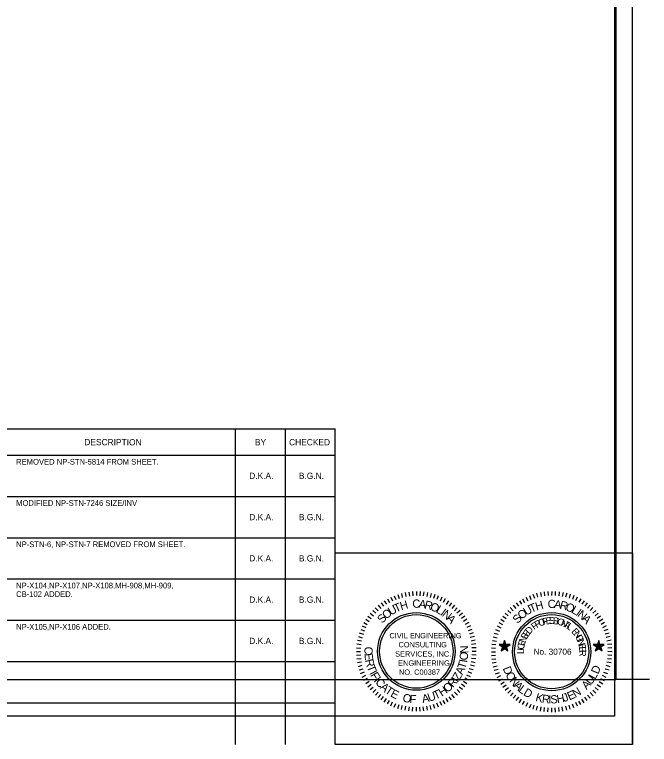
# Model space of a CAD drawing. Extents: x 260980 to 263829, y 322034 to 323393.
# Drawn here: x 262340 to 262786, y 322332 to 322845 of the extents above; entities that cross this region are included whole.
import ezdxf

# ---------------------------------------------------------------- set-up
doc = ezdxf.new("R2010")
doc.units = 0
for name, color, linetype in [('Level 1', 7, 'Continuous'), ('Level 2', 7, 'Continuous'), ('Level 23', 7, 'Continuous'), ('Level 3', 7, 'Continuous'), ('Level 5', 7, 'Continuous'), ('RD_SHT_SEAL_KA', 7, 'Continuous'), ('RD_SHT_TX', 7, 'Continuous')]:
    doc.layers.add(name, color=color, linetype=linetype)

msp = doc.modelspace()

# ---------------------------------------------------------------- linework, layer by layer
at = {"layer": 'Level 1'}
msp.add_lwpolyline([(262565.22, 322466.63), (262774.17, 322466.63), (262774.17, 322331.93), (262565.22, 322331.93)], close=True, dxfattribs=at)
at = {"layer": 'Level 2'}
msp.add_line((262761.95, 322377.79), (262785.98, 322377.79), dxfattribs=at)
at = {"layer": 'Level 23'}
msp.add_lwpolyline([(261111.06, 323336.45), (262761.54, 323336.45), (262761.54, 322351.79), (261111.06, 322351.79)], close=True, dxfattribs=at)
msp.add_lwpolyline([(261111.06, 323336.45), (262761.54, 323336.45), (262761.54, 322351.79), (261111.06, 322351.79)], close=True, dxfattribs=at)
at = {"layer": 'Level 3'}
msp.add_line((262774.17, 322332.83), (262774.17, 323381.93), dxfattribs=at)
at = {"layer": 'Level 5'}
msp.add_lwpolyline([(261111.06, 323310.45), (262762.33, 323310.45), (262762.33, 322377.34), (261111.06, 322377.34)], close=True, dxfattribs=at)
at = {"layer": 'RD_SHT_SEAL_KA'}
for p, q in [((262604.29, 322435.3), (262605.54, 322432.74)), ((262606.76, 322436.43), (262607.81, 322433.69)), ((262609.18, 322437.25), (262610.09, 322434.5)), ((262611.77, 322438.02), (262612.38, 322435.23)), ((262614.37, 322438.65), (262614.85, 322435.76)), ((262617.01, 322438.98), (262617.36, 322436.19)), ((262619.61, 322439.34), (262619.76, 322436.38)), ((262622.25, 322439.41), (262622.24, 322436.5)), ((262624.87, 322439.29), (262624.67, 322436.4)), ((262627.44, 322439.02), (262627.12, 322436.22)), ((262630.06, 322438.63), (262629.58, 322435.89)), ((262632.67, 322437.99), (262631.94, 322435.18)), ((262635.18, 322437.3), (262634.33, 322434.51)), ((262637.64, 322436.38), (262636.7, 322433.73)), ((262640.12, 322435.31), (262638.92, 322432.67)), ((262699.25, 322435.47), (262700.5, 322432.88)), ((262701.68, 322436.55), (262702.77, 322433.79)), ((262704.17, 322437.41), (262705.14, 322434.71)), ((262706.71, 322438.17), (262707.46, 322435.36)), ((262709.41, 322438.76), (262709.89, 322435.85)), ((262712.05, 322439.14), (262712.38, 322436.33)), ((262714.65, 322439.41), (262714.81, 322436.55)), ((262717.35, 322439.46), (262717.29, 322436.66)), ((262719.88, 322439.41), (262719.72, 322436.44)), ((262722.64, 322439.19), (262722.26, 322436.28)), ((262725.28, 322438.76), (262724.74, 322435.95)), ((262727.88, 322438.17), (262727.12, 322435.36)), ((262730.41, 322437.46), (262729.55, 322434.66)), ((262732.95, 322436.55), (262731.87, 322433.85)), ((262735.33, 322435.47), (262734.08, 322432.82)), ((262597.49, 322431.32), (262599.11, 322429.06)), ((262599.73, 322432.75), (262601.21, 322430.41)), ((262601.9, 322434.18), (262603.29, 322431.64)), ((262642.46, 322434.15), (262641.02, 322431.7)), ((262644.8, 322432.73), (262643.2, 322430.33)), ((262646.9, 322431.43), (262645.19, 322428.98)), ((262692.34, 322431.36), (262694.07, 322429.04)), ((262694.61, 322432.88), (262696.12, 322430.5)), ((262696.83, 322434.28), (262698.28, 322431.69)), ((262737.7, 322434.28), (262736.35, 322431.8)), ((262740.08, 322432.88), (262738.51, 322430.45)), ((262742.24, 322431.42), (262740.57, 322428.99)), ((262591.59, 322426.04), (262593.73, 322424.11)), ((262593.36, 322427.97), (262595.45, 322425.89)), ((262595.44, 322429.8), (262597.23, 322427.41)), ((262648.98, 322429.68), (262647.25, 322427.45)), ((262650.99, 322427.92), (262649.01, 322425.88)), ((262652.96, 322426.12), (262650.75, 322424.13)), ((262686.4, 322426.02), (262688.51, 322424.13)), ((262688.18, 322428.01), (262690.29, 322425.86)), ((262690.24, 322429.8), (262692.07, 322427.53)), ((262744.35, 322429.8), (262742.51, 322427.59)), ((262746.34, 322428.01), (262744.45, 322425.91)), ((262748.29, 322426.13), (262746.13, 322424.13)), ((262586.67, 322419.87), (262589.17, 322418.32)), ((262588.19, 322422), (262590.45, 322420.31)), ((262589.71, 322424.13), (262592.03, 322422.26)), ((262654.59, 322424.12), (262652.41, 322422.25)), ((262656.24, 322421.98), (262653.88, 322420.31)), ((262682.95, 322422.02), (262685.38, 322420.29)), ((262684.57, 322424.13), (262686.83, 322422.29)), ((262750.02, 322424.13), (262747.8, 322422.29)), ((262751.58, 322422.02), (262749.31, 322420.35)), ((262584.16, 322415.2), (262586.73, 322413.99)), ((262585.4, 322417.48), (262587.76, 322416.17)), ((262657.74, 322419.83), (262655.32, 322418.33)), ((262659.17, 322417.58), (262656.56, 322416.1)), ((262660.22, 322415.18), (262657.76, 322413.98)), ((262678.9, 322415.16), (262681.49, 322413.92)), ((262680.14, 322417.49), (262682.68, 322416.14)), ((262681.49, 322419.86), (262683.97, 322418.24)), ((262753.15, 322419.81), (262750.72, 322418.3)), ((262754.5, 322417.49), (262752.01, 322416.08)), ((262755.63, 322415.16), (262753.09, 322413.87)), ((262582.17, 322410.26), (262585, 322409.38)), ((262583.12, 322412.76), (262585.72, 322411.67)), ((262661.26, 322412.78), (262658.64, 322411.71)), ((262662.24, 322410.3), (262659.49, 322409.39)), ((262676.95, 322410.14), (262679.71, 322409.28)), ((262677.87, 322412.68), (262680.57, 322411.6)), ((262756.77, 322412.74), (262754.07, 322411.65)), ((262757.68, 322410.2), (262754.93, 322409.28)), ((262580.88, 322405.11), (262583.73, 322404.61)), ((262581.49, 322407.68), (262584.26, 322406.91)), ((262662.98, 322407.67), (262660.15, 322407.09)), ((262663.48, 322405.16), (262660.69, 322404.55)), ((262675.66, 322405.01), (262678.52, 322404.53)), ((262676.2, 322407.6), (262679.06, 322406.9)), ((262758.44, 322407.66), (262755.58, 322406.96)), ((262759.03, 322405.06), (262756.12, 322404.47)), ((262580.27, 322399.82), (262583.12, 322399.65)), ((262580.46, 322402.52), (262583.38, 322402.1)), ((262664.03, 322402.55), (262661.03, 322402.17)), ((262664.22, 322399.89), (262661.3, 322399.71)), ((262675.01, 322399.72), (262677.87, 322399.56)), ((262675.23, 322402.36), (262678.09, 322402.04)), ((262759.47, 322402.36), (262756.55, 322402.1)), ((262759.63, 322399.72), (262756.77, 322399.56)), ((262580.26, 322394.6), (262583.13, 322394.81)), ((262580.29, 322397.29), (262583.05, 322397.26)), ((262664.21, 322394.6), (262661.32, 322394.8)), ((262664.2, 322397.32), (262661.45, 322397.27)), ((262674.95, 322397.07), (262677.82, 322397.07)), ((262674.95, 322394.43), (262677.82, 322394.59)), ((262759.63, 322394.48), (262756.77, 322394.64)), ((262759.73, 322397.07), (262756.87, 322397.13)), ((262580.5, 322392.02), (262583.37, 322392.31)), ((262580.83, 322389.38), (262583.68, 322389.89)), ((262663.49, 322389.33), (262660.66, 322389.87)), ((262663.97, 322392), (262661.03, 322392.3)), ((262675.23, 322391.73), (262678.14, 322392.16)), ((262675.6, 322389.14), (262678.41, 322389.62)), ((262759.03, 322389.14), (262756.12, 322389.68)), ((262759.36, 322391.78), (262756.5, 322392.05)), ((262581.5, 322386.75), (262584.2, 322387.49)), ((262582.25, 322384.31), (262584.94, 322385.13)), ((262662.22, 322384.29), (262659.43, 322385.14)), ((262662.98, 322386.81), (262660.17, 322387.54)), ((262676.25, 322386.49), (262679, 322387.19)), ((262677.01, 322384.01), (262679.71, 322384.87)), ((262757.63, 322384.01), (262754.93, 322384.87)), ((262758.44, 322386.54), (262755.58, 322387.3)), ((262583.09, 322381.73), (262585.82, 322382.86)), ((262584.15, 322379.26), (262586.85, 322380.6)), ((262660.26, 322379.39), (262657.73, 322380.57)), ((262661.3, 322381.83), (262658.64, 322382.84)), ((262677.82, 322381.47), (262680.57, 322382.49)), ((262678.95, 322378.99), (262681.54, 322380.28)), ((262755.68, 322378.99), (262753.09, 322380.28)), ((262756.77, 322381.52), (262754.01, 322382.55)), ((262585.41, 322376.96), (262587.83, 322378.45)), ((262586.73, 322374.74), (262589.18, 322376.27)), ((262588.24, 322372.43), (262590.44, 322374.23)), ((262656.22, 322372.41), (262653.91, 322374.2)), ((262657.77, 322374.58), (262655.26, 322376.2)), ((262659.04, 322376.97), (262656.48, 322378.36)), ((262680.08, 322376.61), (262682.68, 322378.06)), ((262681.54, 322374.34), (262683.87, 322375.85)), ((262683, 322372.13), (262685.32, 322373.85)), ((262751.63, 322372.13), (262749.31, 322373.8)), ((262753.15, 322374.29), (262750.72, 322375.8)), ((262754.5, 322376.66), (262751.96, 322378.01)), ((262589.76, 322370.46), (262591.99, 322372.23)), ((262591.57, 322368.45), (262593.75, 322370.4)), ((262593.44, 322366.6), (262595.45, 322368.68)), ((262651.03, 322366.58), (262648.97, 322368.71)), ((262652.88, 322368.45), (262650.81, 322370.39)), ((262654.68, 322370.43), (262652.41, 322372.19)), ((262684.62, 322370.07), (262686.89, 322371.86)), ((262686.4, 322368.02), (262688.51, 322370.02)), ((262748.23, 322368.02), (262746.18, 322370.02)), ((262750.07, 322370.07), (262747.8, 322371.91)), ((262595.46, 322364.77), (262597.19, 322367)), ((262597.51, 322363.24), (262599.2, 322365.5)), ((262599.64, 322361.72), (262601.2, 322364.15)), ((262644.7, 322361.77), (262643.22, 322364.11)), ((262646.9, 322363.23), (262645.25, 322365.45)), ((262648.95, 322364.76), (262647.25, 322367)), ((262688.35, 322366.08), (262690.24, 322368.24)), ((262690.29, 322364.4), (262692.07, 322366.56)), ((262692.4, 322362.79), (262694.13, 322365.05)), ((262694.56, 322361.22), (262696.12, 322363.7)), ((262740.03, 322361.22), (262738.51, 322363.65)), ((262742.29, 322362.79), (262740.62, 322365.11)), ((262744.29, 322364.35), (262742.51, 322366.56)), ((262746.4, 322366.13), (262744.4, 322368.29)), ((262601.97, 322360.37), (262603.34, 322362.81)), ((262604.32, 322359.14), (262605.51, 322361.85)), ((262606.72, 322358.13), (262607.81, 322360.73)), ((262609.22, 322357.18), (262610.07, 322359.97)), ((262611.8, 322356.5), (262612.38, 322359.29)), ((262614.33, 322355.92), (262614.83, 322358.77)), ((262616.93, 322355.42), (262617.34, 322358.34)), ((262627.43, 322355.47), (262627.1, 322358.37)), ((262630.02, 322355.91), (262629.59, 322358.68)), ((262632.66, 322356.5), (262631.98, 322359.28)), ((262635.18, 322357.19), (262634.32, 322359.91)), ((262637.71, 322358.14), (262636.63, 322360.83)), ((262640.18, 322359.19), (262638.92, 322361.83)), ((262642.49, 322360.37), (262641.14, 322362.81)), ((262696.88, 322359.92), (262698.28, 322362.41)), ((262699.31, 322358.68), (262700.5, 322361.33)), ((262701.63, 322357.6), (262702.82, 322360.3)), ((262704.22, 322356.74), (262705.03, 322359.49)), ((262706.76, 322355.93), (262707.41, 322358.79)), ((262727.88, 322355.98), (262727.23, 322358.79)), ((262730.41, 322356.74), (262729.55, 322359.44)), ((262732.95, 322357.6), (262731.87, 322360.3)), ((262735.43, 322358.74), (262734.19, 322361.33)), ((262737.7, 322359.92), (262736.35, 322362.41)), ((262619.63, 322355.24), (262619.79, 322358.17)), ((262622.25, 322355.2), (262622.23, 322357.99)), ((262624.92, 322355.23), (262624.74, 322358.15)), ((262709.35, 322355.39), (262709.89, 322358.3)), ((262712, 322355.01), (262712.38, 322357.87)), ((262714.7, 322354.74), (262714.86, 322357.6)), ((262717.35, 322354.69), (262717.35, 322357.55)), ((262719.99, 322354.63), (262719.83, 322357.65)), ((262722.58, 322355.01), (262722.26, 322357.87)), ((262725.23, 322355.39), (262724.74, 322358.25))]:
    msp.add_line(p, q, dxfattribs=at)
for points in [[(262684.24, 322405.01), (262683.33, 322402.15), (262680.41, 322402.15), (262682.78, 322400.37), (262681.81, 322397.67), (262684.3, 322399.4), (262686.62, 322397.67), (262685.7, 322400.42), (262688.08, 322402.2), (262685.16, 322402.2)], [(262684.19, 322404.58), (262683.43, 322402.1), (262680.73, 322402.1), (262682.84, 322400.48), (262682.08, 322397.94), (262684.19, 322399.56), (262686.35, 322397.94), (262685.54, 322400.53), (262687.75, 322402.04), (262685.11, 322402.1)], [(262750.39, 322405.01), (262749.42, 322402.2), (262746.56, 322402.15), (262748.93, 322400.42), (262747.96, 322397.61), (262750.39, 322399.4), (262752.77, 322397.61), (262751.8, 322400.42), (262754.23, 322402.2), (262751.26, 322402.2)], [(262750.34, 322404.64), (262749.53, 322402.1), (262746.88, 322402.04), (262749.1, 322400.42), (262748.29, 322397.94), (262750.39, 322399.45), (262752.55, 322397.94), (262751.74, 322400.48), (262753.9, 322402.1), (262751.2, 322402.04)], [(262684.3, 322404.2), (262683.43, 322401.94), (262681.11, 322401.94), (262683.05, 322400.53), (262682.35, 322398.26), (262684.24, 322399.66), (262686.19, 322398.21), (262685.38, 322400.59), (262687.38, 322401.88), (262685, 322401.94)], [(262684.3, 322403.82), (262683.54, 322401.83), (262681.49, 322401.77), (262683.22, 322400.59), (262682.57, 322398.59), (262684.19, 322399.83), (262685.97, 322398.59), (262685.38, 322400.59), (262687, 322401.88), (262684.89, 322401.77)], [(262684.24, 322403.45), (262683.7, 322401.72), (262681.87, 322401.66), (262683.33, 322400.64), (262682.73, 322398.86), (262684.24, 322399.99), (262685.75, 322398.86), (262685.16, 322400.64), (262686.57, 322401.72), (262684.89, 322401.72)], [(262684.24, 322403.07), (262683.81, 322401.56), (262682.25, 322401.61), (262683.49, 322400.69), (262683, 322399.24), (262684.3, 322400.15), (262685.54, 322399.18), (262685, 322400.69), (262686.3, 322401.5), (262684.73, 322401.56)], [(262684.24, 322402.64), (262683.87, 322401.5), (262682.62, 322401.34), (262683.65, 322400.75), (262683.27, 322399.56), (262684.19, 322400.26), (262685.32, 322399.5), (262684.95, 322400.75), (262685.86, 322401.45), (262684.62, 322401.45)], [(262684.24, 322402.26), (262683.97, 322401.34), (262683, 322401.34), (262683.81, 322400.8), (262683.49, 322399.88), (262684.24, 322400.37), (262685.05, 322399.83), (262684.78, 322400.75), (262685.54, 322401.29), (262684.51, 322401.39)], [(262684.24, 322401.83), (262684.03, 322401.23), (262683.33, 322401.23), (262683.87, 322400.8), (262683.76, 322400.21), (262684.3, 322400.59), (262684.73, 322400.15), (262684.62, 322400.8), (262685.16, 322401.18), (262684.46, 322401.23)], [(262684.3, 322401.5), (262684.08, 322401.12), (262683.76, 322401.12), (262684.08, 322400.85), (262683.92, 322400.48), (262684.3, 322400.75), (262684.51, 322400.48), (262684.4, 322400.91), (262684.73, 322401.07), (262684.4, 322401.07)], [(262684.3, 322401.07), (262684.24, 322400.91), (262684.03, 322400.96), (262684.19, 322400.96), (262684.13, 322400.8), (262684.24, 322400.8), (262684.3, 322400.8), (262684.3, 322400.91), (262684.46, 322401.01), (262684.3, 322401.01)], [(262750.39, 322404.2), (262749.69, 322401.88), (262747.26, 322401.94), (262749.2, 322400.53), (262748.5, 322398.21), (262750.39, 322399.66), (262752.34, 322398.26), (262751.58, 322400.48), (262753.53, 322401.99), (262751.15, 322401.94)], [(262750.34, 322403.82), (262749.75, 322401.77), (262747.64, 322401.77), (262749.42, 322400.59), (262748.61, 322398.64), (262750.39, 322399.83), (262752.07, 322398.64), (262751.42, 322400.59), (262753.15, 322401.83), (262751.04, 322401.83)], [(262750.34, 322403.39), (262749.8, 322401.66), (262747.96, 322401.72), (262749.42, 322400.69), (262748.93, 322398.86), (262750.34, 322399.94), (262751.8, 322398.91), (262751.31, 322400.59), (262752.82, 322401.66), (262750.93, 322401.72)], [(262750.45, 322403.01), (262749.91, 322401.61), (262748.34, 322401.61), (262749.64, 322400.75), (262749.1, 322399.18), (262750.39, 322400.1), (262751.58, 322399.24), (262751.2, 322400.64), (262752.34, 322401.56), (262750.88, 322401.61)], [(262750.39, 322402.64), (262749.96, 322401.5), (262748.72, 322401.45), (262749.8, 322400.69), (262749.37, 322399.56), (262750.39, 322400.31), (262751.37, 322399.5), (262750.99, 322400.75), (262752.07, 322401.45), (262750.77, 322401.5)], [(262750.39, 322402.2), (262750.12, 322401.34), (262749.1, 322401.34), (262749.91, 322400.75), (262749.58, 322399.88), (262750.39, 322400.37), (262751.15, 322399.83), (262750.88, 322400.75), (262751.58, 322401.34), (262750.66, 322401.34)], [(262750.39, 322401.88), (262750.07, 322401.23), (262749.53, 322401.18), (262750.02, 322400.85), (262749.8, 322400.21), (262750.39, 322400.53), (262750.93, 322400.15), (262750.72, 322400.75), (262751.31, 322401.18), (262750.66, 322401.23)], [(262750.34, 322401.5), (262750.28, 322401.12), (262749.85, 322401.12), (262750.23, 322400.85), (262750.02, 322400.48), (262750.45, 322400.69), (262750.72, 322400.48), (262750.55, 322400.8), (262750.93, 322401.12), (262750.55, 322401.07)], [(262750.45, 322401.07), (262750.39, 322400.96), (262750.23, 322400.96), (262750.28, 322400.91), (262750.28, 322400.75), (262750.34, 322400.85), (262750.5, 322400.85), (262750.45, 322400.91), (262750.5, 322400.96), (262750.39, 322400.91)]]:
    msp.add_lwpolyline(points, close=True, dxfattribs=at)
for radius in [27.48, 26.04]:
    msp.add_circle((262717.31, 322397.08), radius, dxfattribs=at)
for major_axis in [(0.01, 27.28), (0.01, 25.84)]:
    msp.add_ellipse((262622.22, 322397.26), major_axis=major_axis, ratio=0.998589, dxfattribs=at)
at = {"layer": 'RD_SHT_TX'}
for p, q in [((262254.62, 322553.63), (262565.22, 322553.63)), ((262495.22, 322331.93), (262495.22, 322553.63)), ((262530.22, 322331.93), (262530.22, 322553.63)), ((262565.22, 322389.92), (262565.22, 322553.63)), ((262565.22, 322534.93), (262254.62, 322534.93)), ((262565.22, 322505.93), (262254.62, 322505.93)), ((262565.22, 322476.93), (262254.62, 322476.93)), ((262565.22, 322447.93), (262254.62, 322447.93)), ((262565.22, 322418.93), (262254.62, 322418.93)), ((262565.22, 322389.93), (262254.62, 322389.93)), ((262565.22, 322360.93), (262254.62, 322360.93))]:
    msp.add_line(p, q, dxfattribs=at)

# ---------------------------------------------------------------- texts
at = {"layer": 'RD_SHT_SEAL_KA'}
for s, height, rotation, p in [('T', 5.79, 23.2887, (262607.89, 322424.49)), ('H', 5.79, 15.7743, (262611.58, 322426.13)), ('C', 5.79, 0.6858, (262619.46, 322427.9)), ('A', 5.79, 352.8136, (262623.68, 322427.99)), ('R', 5.79, 345.657, (262627.5, 322427.57)), ('O', 5.79, 338.1426, (262631.42, 322426.62)), ('T', 5.79, 23.2887, (262702.99, 322424.31)), ('H', 5.79, 15.7743, (262706.67, 322425.95)), ('C', 5.79, 0.6858, (262714.55, 322427.72)), ('A', 5.79, 352.8136, (262718.78, 322427.81)), ('R', 5.79, 345.657, (262722.59, 322427.39)), ('O', 5.79, 338.1426, (262726.51, 322426.44)), ('O', 5.79, 39.0332, (262601.04, 322419.58)), ('U', 5.79, 30.8031, (262604.45, 322422.38)), ('L', 5.79, 329.9125, (262635.52, 322425)), ('I', 5.79, 323.1138, (262638.71, 322423.23)), ('N', 5.79, 320.609, (262639.83, 322422.48)), ('O', 5.79, 39.0332, (262696.14, 322419.4)), ('U', 5.79, 30.8031, (262699.55, 322422.2)), ('L', 5.79, 329.9125, (262730.62, 322424.82)), ('I', 5.79, 323.1138, (262733.81, 322423.05)), ('N', 5.79, 320.609, (262734.93, 322422.3)), ('S', 5.79, 46.5476, (262598.3, 322416.62)), ('A', 5.79, 313.0946, (262642.98, 322419.96)), ('S', 5.79, 46.5476, (262693.4, 322416.44)), ('O', 4.82, 21.7793, (262708.87, 322414.62)), ('F', 4.82, 14.3582, (262711.21, 322415.56)), ('E', 4.82, 7.9051, (262713.32, 322416.13)), ('S', 4.82, 1.452, (262715.49, 322416.45)), ('S', 4.82, 354.6762, (262717.79, 322416.53)), ('I', 4.82, 347.9004, (262720.08, 322416.33)), ('O', 4.82, 345.6418, (262720.84, 322416.2)), ('A', 5.79, 313.0946, (262738.08, 322419.78)), ('P', 4.82, 35.3308, (262704.99, 322412.16)), ('R', 4.82, 28.555, (262706.86, 322413.51)), ('N', 4.82, 338.2207, (262723.28, 322415.58)), ('A', 4.82, 331.445, (262725.42, 322414.75)), ('L', 4.82, 324.9919, (262727.36, 322413.72)), ('CIVIL ENGINEERING', 3.7513, 359.9897, (262603.32, 322406.46)), ('S', 4.82, 62.165, (262699.5, 322404.99)), ('E', 4.82, 55.3892, (262700.56, 322407.03)), ('D', 4.82, 48.9361, (262701.78, 322408.85)), ('E', 4.82, 312.0319, (262730.83, 322411.04)), ('N', 4.82, 305.5788, (262732.32, 322409.42)), ('E', 4.82, 75.3939, (262698.16, 322400.71)), ('N', 4.82, 68.9407, (262698.69, 322402.84)), ('G', 4.82, 298.803, (262733.67, 322407.56)), ('I', 4.82, 291.7046, (262734.84, 322405.46)), ('N', 4.82, 289.446, (262735.16, 322404.76)), ('C', 5.79, 268.515, (262585.83, 322400.71)), ('CONSULTING', 3.751, 359.9897, (262609.7, 322400.11)), ('N', 5.79, 91.8428, (262658.74, 322395.93)), ('C', 4.82, 82.4923, (262697.86, 322398.32)), ('E', 4.82, 282.6702, (262735.94, 322402.59)), ('E', 4.82, 276.2171, (262736.44, 322400.46)), ('E', 5.79, 276.3872, (262585.7, 322395.7)), ('SERVICES, INC.', 3.7513, 359.9897, (262607.31, 322393.62)), ('O', 5.79, 83.6128, (262658.17, 322390.72)), ('L', 4.82, 90.8813, (262697.88, 322395.47)), ('I', 4.82, 84.7509, (262697.82, 322397.55)), ('R', 4.82, 269.764, (262736.7, 322398.29)), ('R', 5.79, 283.5438, (262586.18, 322391.16)), ('ENGINEERING', 3.7513, 359.9897, (262609.45, 322387.19)), ('T', 5.79, 73.5935, (262656.48, 322384.56)), ('I', 5.79, 81.108, (262657.85, 322389.15)), ('T', 5.79, 291.0582, (262587.29, 322386.5)), ('I', 5.79, 298.5727, (262589, 322382.02)), ('NO. C00387', 3.751, 359.9897, (262610.06, 322380.82)), ('A', 5.79, 66.437, (262654.63, 322380.39)), ('D', 5.78, 292.563, (262682.8, 322385.32)), ('D', 5.78, 67.437, (262749.99, 322380.91)), ('F', 5.79, 301.0775, (262589.7, 322380.59)), ('I', 5.79, 308.234, (262592.03, 322376.67)), ('I', 5.79, 56.4177, (262651.2, 322375.01)), ('Z', 5.79, 58.9225, (262652.15, 322376.3)), ('O', 5.78, 300.0892, (262684.64, 322380.91)), ('N', 5.78, 308.3321, (262687.29, 322376.39)), ('U', 5.78, 53.1014, (262744.97, 322373.32)), ('L', 5.78, 60.6276, (262747.84, 322377.15)), ('C', 5.79, 310.7388, (262592.96, 322375.37)), ('A', 5.79, 318.6111, (262596.23, 322371.57)), ('O', 5.79, 40.6733, (262644.08, 322367.98)), ('R', 5.79, 48.9033, (262648.04, 322371.41)), ('A', 5.78, 315.8583, (262690.26, 322372.63)), ('A', 5.78, 45.9336, (262741.79, 322370.06)), ('T', 5.79, 325.7677, (262599.64, 322368.53)), ('E', 5.79, 333.2821, (262603.59, 322365.82)), ('U', 5.79, 18.13, (262631.18, 322361.83)), ('T', 5.79, 25.6444, (262635.74, 322363.31)), ('H', 5.79, 33.1588, (262640.06, 322365.37)), ('L', 5.78, 323.0261, (262693.52, 322369.45)), ('D', 5.78, 329.8355, (262696.96, 322366.82)), ('E', 5.78, 23.6537, (262729.72, 322362.8)), ('N', 5.78, 30.8215, (262733.9, 322364.61)), ('O', 5.79, 348.0127, (262612.19, 322362.12)), ('F', 5.79, 356.2428, (262617.33, 322361.05)), ('A', 5.79, 10.9734, (262626.7, 322360.99)), ('K', 5.78, 344.9476, (262705.56, 322362.57)), ('R', 5.78, 352.4738, (262710.18, 322361.32)), ('I', 5.78, 360, (262714.92, 322360.7)), ('S', 5.78, 2.5087, (262716.52, 322360.63)), ('H', 5.78, 10.0349, (262721.3, 322360.84)), ('J', 5.78, 17.5611, (262726.01, 322361.67))]:
    msp.add_text(s, height=height, rotation=rotation, dxfattribs=at).set_placement(p)
msp.add_text('No. 30706', height=4.336, dxfattribs=at).set_placement((262704.54, 322394.9))
at = {"layer": 'RD_SHT_TX'}
for s, height, rotation, p in [('DESCRIPTION', 4.4083, 359.7246, (262388.92, 322542.17)), ('BY', 4.408, 359.7246, (262508.77, 322542.09)), ('REMOVED NP-STN-5814 FROM SHEET.', 4, 360, (262341.03, 322528.54)), ('D.K.A.', 4.4, 360, (262504.81, 322518.45)), ('B.G.N.', 4.4, 360, (262539.68, 322518.45)), ('MODIFIED NP-STN-7246 SIZE/INV', 4, 360, (262341.03, 322499.54)), ('D.K.A.', 4.4, 360, (262504.81, 322489.45)), ('B.G.N.', 4.4, 360, (262539.69, 322489.45)), ('NP-STN-6, NP-STN-7 REMOVED FROM SHEET.', 4, 360, (262341.03, 322470.54)), ('D.K.A.', 4.4, 360, (262504.81, 322460.45)), ('B.G.N.', 4.4, 360, (262539.69, 322460.45)), ('NP-X104,NP-X107,NP-X108,MH-908,MH-909,', 4, 360, (262341.03, 322441.54)), ('CB-102 ADDED.', 4, 360, (262341.03, 322435.54)), ('D.K.A.', 4.4, 360, (262504.81, 322431.45)), ('B.G.N.', 4.4, 360, (262539.69, 322431.45)), ('NP-X105,NP-X106 ADDED.', 4, 360, (262341.03, 322412.54)), ('D.K.A.', 4.4, 360, (262504.81, 322402.45)), ('B.G.N.', 4.4, 360, (262539.69, 322402.45))]:
    msp.add_text(s, height=height, rotation=rotation, dxfattribs=at).set_placement(p)
msp.add_text('CHECKED', height=4.4, dxfattribs=at).set_placement((262532.82, 322542.05))

doc.saveas('drawing.dxf')
